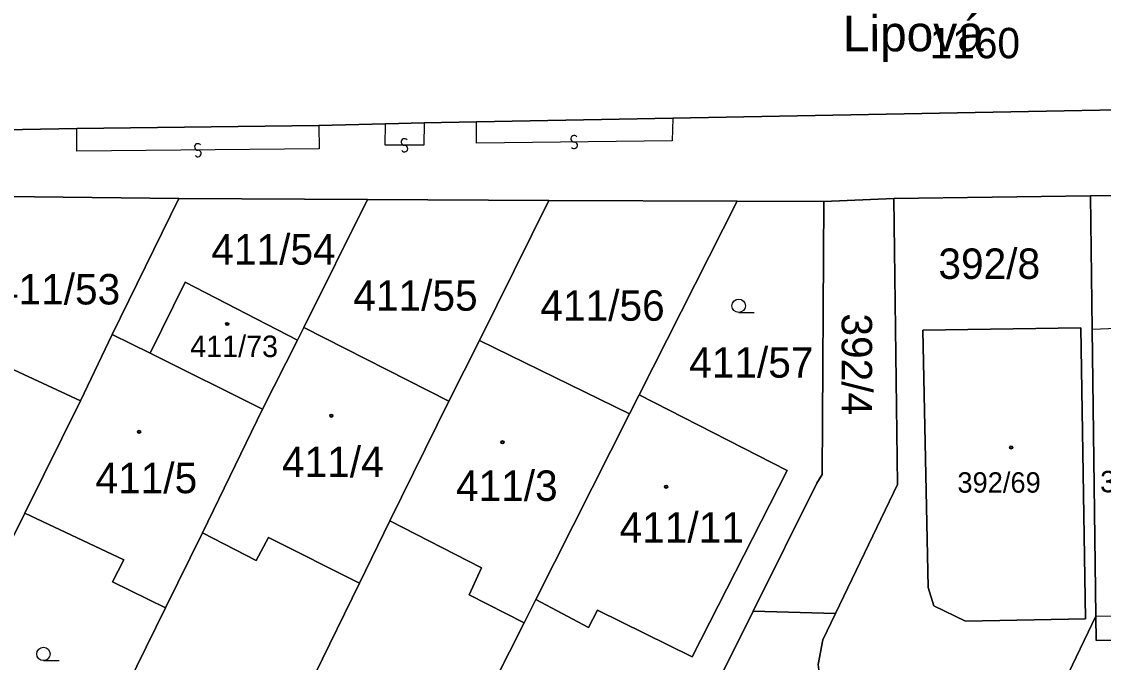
# Model space of a CAD drawing. Extents: x -600309 to -598967, y -1161267 to -1160292.
# Drawn here: x -599934.1 to -599873.6, y -1160656.9 to -1160621.1 of the extents above; entities that cross this region are included whole.
import ezdxf

# ---------------------------------------------------------------- set-up
doc = ezdxf.new("R2010")
doc.units = 0
for name, color, linetype in [('Level 1', 7, 'Continuous'), ('Level 11', 7, 'Continuous'), ('Level 13', 7, 'Continuous'), ('Level 3', 7, 'Continuous'), ('Level 4', 7, 'Continuous'), ('Level 5', 7, 'Continuous'), ('Level 60', 7, 'Continuous')]:
    doc.layers.add(name, color=color, linetype=linetype)

msp = doc.modelspace()

# ---------------------------------------------------------------- linework, layer by layer
at = {"layer": 'Level 1'}
for points in [[(-599756.08, -1160616.21), (-599758.31, -1160616.61), (-599802.91, -1160623.13), (-599821.1, -1160624.93), (-599822.46, -1160624.97), (-599824.85, -1160625.23), (-599827.9, -1160625.24), (-599856.9, -1160625.7), (-599897.68, -1160626.45)], [(-599822.46, -1160624.97), (-599824.85, -1160625.23), (-599827.9, -1160625.24), (-599856.9, -1160625.7), (-599897.68, -1160626.45), (-599908.66, -1160626.66), (-599911.59, -1160626.72), (-599913.75, -1160626.78), (-599917.47, -1160626.86), (-599931.02, -1160627.04), (-599938.13, -1160627.17), (-599938.52, -1160627.22), (-599945.69, -1160627.27), (-599947.92, -1160619.35)], [(-599897.68, -1160626.45), (-599908.66, -1160626.66)], [(-599931.02, -1160627.04), (-599938.13, -1160627.17)], [(-599931.02, -1160627.04), (-599917.47, -1160626.86)], [(-599913.75, -1160626.78), (-599917.47, -1160626.86)], [(-599913.75, -1160626.78), (-599911.59, -1160626.72)], [(-599908.66, -1160626.66), (-599911.59, -1160626.72)], [(-599935.01, -1160630.83), (-599925.3, -1160630.95)], [(-599874.33, -1160630.8), (-599885.33, -1160630.94)], [(-599868.33, -1160630.72), (-599874.33, -1160630.8)], [(-599874.33, -1160630.8), (-599874.23, -1160638.25)], [(-599925.3, -1160630.95), (-599929.03, -1160638.55)], [(-599925.3, -1160630.95), (-599914.76, -1160631)], [(-599914.76, -1160631), (-599918.31, -1160638.16)], [(-599914.76, -1160631), (-599904.62, -1160631.05)], [(-599904.62, -1160631.05), (-599908.5, -1160638.88)], [(-599904.62, -1160631.05), (-599894.08, -1160631.09)], [(-599894.08, -1160631.09), (-599899.56, -1160641.92)], [(-599894.08, -1160631.09), (-599889.23, -1160631.12)], [(-599893.19, -1160654.01), (-599889.63, -1160646.85), (-599889.34, -1160646.37), (-599889.23, -1160631.12)], [(-599885.33, -1160630.94), (-599889.23, -1160631.12)], [(-599885.33, -1160630.94), (-599885.12, -1160646.94), (-599888.59, -1160654.14)], [(-599926.91, -1160639.6), (-599924.95, -1160635.63), (-599918.67, -1160638.87)], [(-599938.77, -1160638.56), (-599930.8, -1160642.25)], [(-599930.8, -1160642.25), (-599929.03, -1160638.55)], [(-599929.03, -1160638.55), (-599926.91, -1160639.6)], [(-599918.67, -1160638.87), (-599918.31, -1160638.16)], [(-599918.31, -1160638.16), (-599910.21, -1160642.27)], [(-599883.7, -1160638.31), (-599883.4, -1160652.69), (-599883.09, -1160653.71), (-599881.31, -1160654.58), (-599874.61, -1160654.44), (-599874.86, -1160638.18), (-599883.7, -1160638.31)], [(-599874.02, -1160654.3), (-599874.23, -1160638.25)], [(-599920.62, -1160642.72), (-599918.67, -1160638.87)], [(-599910.21, -1160642.27), (-599908.5, -1160638.88)], [(-599908.5, -1160638.88), (-599900.1, -1160642.99)], [(-599926.91, -1160639.6), (-599920.62, -1160642.72)], [(-599933.92, -1160648.54), (-599930.8, -1160642.25)], [(-599913.5, -1160648.97), (-599910.21, -1160642.27)], [(-599899.56, -1160641.92), (-599891.28, -1160646.15), (-599896.6, -1160656.57), (-599901.9, -1160653.95), (-599902.4, -1160654.92), (-599905.35, -1160653.37)], [(-599900.1, -1160642.99), (-599899.56, -1160641.92)], [(-599923.99, -1160649.63), (-599920.62, -1160642.72)], [(-599900.1, -1160642.99), (-599905.35, -1160653.37)], [(-599933.92, -1160648.54), (-599935.97, -1160652.66)], [(-599926.06, -1160653.83), (-599929.01, -1160652.38), (-599928.38, -1160651.14), (-599933.92, -1160648.54)], [(-599913.5, -1160648.97), (-599915.2, -1160652.44)], [(-599906, -1160654.66), (-599909.08, -1160653.1), (-599908.38, -1160651.59), (-599913.5, -1160648.97)], [(-599923.99, -1160649.63), (-599926.06, -1160653.83)], [(-599915.2, -1160652.44), (-599920.29, -1160649.9), (-599920.98, -1160651.19), (-599923.99, -1160649.63)], [(-599922.27, -1160666.88), (-599915.2, -1160652.44)], [(-599931.96, -1160665.84), (-599926.06, -1160653.83)], [(-599905.35, -1160653.37), (-599906, -1160654.66)], [(-599897.98, -1160663.63), (-599893.19, -1160654.01)], [(-599888.59, -1160654.14), (-599893.19, -1160654.01)], [(-599888.87, -1160659.48), (-599889.38, -1160658.34), (-599889.56, -1160656.99), (-599889.3, -1160655.61), (-599888.59, -1160654.14)], [(-599874.02, -1160654.3), (-599878.84, -1160664.31)], [(-599874.02, -1160654.3), (-599874, -1160655.65), (-599868, -1160655.57)], [(-599914.18, -1160670.83), (-599906, -1160654.66)]]:
    msp.add_lwpolyline(points, dxfattribs=at)
at = {"layer": 'Level 13'}
for centre, start, end in [((-599912.689, -1160627.786), 37.15828, 269.74828), ((-599903.201, -1160627.606), 37.78615, 270.37615), ((-599903.2, -1160627.974), 218.00061, 90.09861), ((-599924.241, -1160628.066), 37.70756, 270.29756), ((-599924.24, -1160628.434), 217.92201, 90.02001), ((-599912.692, -1160628.154), 217.37273, 89.47073)]:
    msp.add_arc(centre, 0.184, start, end, dxfattribs=at)
at = {"layer": 'Level 3'}
for points in [[(-599897.68, -1160626.45), (-599897.72, -1160627.73), (-599908.67, -1160627.85), (-599908.66, -1160626.66)], [(-599917.47, -1160626.86), (-599917.46, -1160628.18), (-599931.02, -1160628.31), (-599931.02, -1160627.04)], [(-599911.59, -1160626.72), (-599911.61, -1160627.97), (-599913.76, -1160627.97), (-599913.75, -1160626.78)], [(-599874.23, -1160638.25), (-599868.24, -1160638.01)], [(-599874.02, -1160654.3), (-599868.03, -1160654.19)]]:
    msp.add_lwpolyline(points, dxfattribs=at)
at = {"layer": 'Level 5'}
for p, q in [((-599894, -1160637.32), (-599893.125, -1160637.32)), ((-599932.88, -1160656.78), (-599932.005, -1160656.78))]:
    msp.add_line(p, q, dxfattribs=at)
for centre, radius in [((-599894, -1160636.945), 0.375), ((-599922.6, -1160637.96), 0.09), ((-599922.6, -1160637.96), 0.0521), ((-599916.78, -1160643.09), 0.09), ((-599916.78, -1160643.09), 0.0521), ((-599927.53, -1160643.99), 0.09), ((-599927.53, -1160643.99), 0.0521), ((-599907.21, -1160644.57), 0.09), ((-599907.21, -1160644.57), 0.0521), ((-599878.76, -1160644.86), 0.09), ((-599878.76, -1160644.86), 0.0521), ((-599898.06, -1160647.06), 0.09), ((-599898.06, -1160647.06), 0.0521), ((-599932.88, -1160656.405), 0.375)]:
    msp.add_circle(centre, radius, dxfattribs=at)
at = {"layer": 'Level 60'}
for points in [[(-599823.51, -1160617.04), (-599822.46, -1160624.97), (-599824.85, -1160625.23), (-599827.9, -1160625.24), (-599856.9, -1160625.7), (-599897.68, -1160626.45), (-599908.66, -1160626.66), (-599911.59, -1160626.72), (-599913.75, -1160626.78), (-599917.47, -1160626.86), (-599931.02, -1160627.04), (-599938.13, -1160627.17), (-599938.52, -1160627.22), (-599945.69, -1160627.27), (-599947.92, -1160619.35)], [(-599868.33, -1160630.72), (-599874.33, -1160630.8), (-599885.33, -1160630.94), (-599889.23, -1160631.12), (-599894.08, -1160631.09), (-599904.62, -1160631.05), (-599914.76, -1160631), (-599925.3, -1160630.95), (-599935.01, -1160630.83), (-599944.67, -1160630.86), (-599945.32, -1160628.56), (-599945.69, -1160627.27), (-599938.52, -1160627.22), (-599938.13, -1160627.17), (-599931.02, -1160627.04), (-599917.47, -1160626.86), (-599913.75, -1160626.78), (-599911.59, -1160626.72), (-599908.66, -1160626.66), (-599897.68, -1160626.45), (-599856.9, -1160625.7)]]:
    msp.add_lwpolyline(points, dxfattribs=at)
for points in [[(-599929.03, -1160638.55), (-599930.8, -1160642.25), (-599938.77, -1160638.56), (-599935.01, -1160630.83), (-599925.3, -1160630.95)], [(-599885.33, -1160630.94), (-599874.33, -1160630.8), (-599874.23, -1160638.25), (-599874.02, -1160654.3), (-599878.84, -1160664.31), (-599888.87, -1160659.48), (-599889.38, -1160658.34), (-599889.56, -1160656.99), (-599889.3, -1160655.61), (-599888.59, -1160654.14), (-599885.12, -1160646.94)], [(-599874.33, -1160630.8), (-599868.33, -1160630.72), (-599868.24, -1160638.01), (-599868.03, -1160654.19), (-599868, -1160655.57), (-599874, -1160655.65), (-599874.02, -1160654.3), (-599874.23, -1160638.25)], [(-599929.03, -1160638.55), (-599925.3, -1160630.95), (-599914.76, -1160631), (-599918.31, -1160638.16), (-599918.67, -1160638.87), (-599924.95, -1160635.63), (-599926.91, -1160639.6)], [(-599908.5, -1160638.88), (-599910.21, -1160642.27), (-599918.31, -1160638.16), (-599914.76, -1160631), (-599904.62, -1160631.05)], [(-599889.63, -1160646.85), (-599893.19, -1160654.01), (-599897.98, -1160663.63), (-599899.94, -1160667.56), (-599903.81, -1160676), (-599913.11, -1160671.36), (-599914.18, -1160670.83), (-599906, -1160654.66), (-599905.35, -1160653.37), (-599902.4, -1160654.92), (-599901.9, -1160653.95), (-599896.6, -1160656.57), (-599891.28, -1160646.15), (-599899.56, -1160641.92), (-599894.08, -1160631.09), (-599889.23, -1160631.12), (-599889.34, -1160646.37)], [(-599900.1, -1160642.99), (-599908.5, -1160638.88), (-599904.62, -1160631.05), (-599894.08, -1160631.09), (-599899.56, -1160641.92)], [(-599885.33, -1160630.94), (-599885.12, -1160646.94), (-599888.59, -1160654.14), (-599893.19, -1160654.01), (-599889.63, -1160646.85), (-599889.34, -1160646.37), (-599889.23, -1160631.12)], [(-599920.62, -1160642.72), (-599926.91, -1160639.6), (-599924.95, -1160635.63), (-599918.67, -1160638.87)], [(-599930.8, -1160642.25), (-599933.92, -1160648.54), (-599935.97, -1160652.66), (-599941.32, -1160650.24), (-599941.82, -1160651.21), (-599944.35, -1160650.02), (-599940.56, -1160642.17), (-599938.77, -1160638.56)], [(-599920.62, -1160642.72), (-599923.99, -1160649.63), (-599926.06, -1160653.83), (-599929.01, -1160652.38), (-599928.38, -1160651.14), (-599933.92, -1160648.54), (-599930.8, -1160642.25), (-599929.03, -1160638.55), (-599926.91, -1160639.6)], [(-599910.21, -1160642.27), (-599913.5, -1160648.97), (-599915.2, -1160652.44), (-599920.29, -1160649.9), (-599920.98, -1160651.19), (-599923.99, -1160649.63), (-599920.62, -1160642.72), (-599918.67, -1160638.87), (-599918.31, -1160638.16)], [(-599874.86, -1160638.18), (-599883.7, -1160638.31), (-599883.4, -1160652.69), (-599883.09, -1160653.71), (-599881.31, -1160654.58), (-599874.61, -1160654.44)], [(-599883.7, -1160638.31), (-599874.86, -1160638.18), (-599874.61, -1160654.44), (-599881.31, -1160654.58), (-599883.09, -1160653.71), (-599883.4, -1160652.69)], [(-599908.5, -1160638.88), (-599900.1, -1160642.99), (-599905.35, -1160653.37), (-599906, -1160654.66), (-599909.08, -1160653.1), (-599908.38, -1160651.59), (-599913.5, -1160648.97), (-599910.21, -1160642.27)], [(-599905.35, -1160653.37), (-599900.1, -1160642.99), (-599899.56, -1160641.92), (-599891.28, -1160646.15), (-599896.6, -1160656.57), (-599901.9, -1160653.95), (-599902.4, -1160654.92)], [(-599929.01, -1160652.38), (-599926.06, -1160653.83), (-599931.96, -1160665.84), (-599940.61, -1160664.91), (-599941.07, -1160664.84), (-599941.57, -1160664.79), (-599935.97, -1160652.66), (-599933.92, -1160648.54), (-599928.38, -1160651.14)], [(-599909.08, -1160653.1), (-599906, -1160654.66), (-599914.18, -1160670.83), (-599921.42, -1160667.28), (-599922.27, -1160666.88), (-599915.2, -1160652.44), (-599913.5, -1160648.97), (-599908.38, -1160651.59)], [(-599920.29, -1160649.9), (-599915.2, -1160652.44), (-599922.27, -1160666.88), (-599931.08, -1160665.93), (-599931.96, -1160665.84), (-599926.06, -1160653.83), (-599923.99, -1160649.63), (-599920.98, -1160651.19)], [(-599893.19, -1160654.01), (-599888.59, -1160654.14), (-599889.3, -1160655.61), (-599889.56, -1160656.99), (-599889.38, -1160658.34), (-599888.87, -1160659.48), (-599888.48, -1160660.23), (-599890.81, -1160659.09), (-599891.24, -1160660.27), (-599893.86, -1160665.64), (-599897.98, -1160663.63)], [(-599878.84, -1160664.31), (-599874.02, -1160654.3), (-599874, -1160655.65), (-599868, -1160655.57), (-599868.01, -1160655.64), (-599873.51, -1160667.04)]]:
    msp.add_lwpolyline(points, close=True, dxfattribs=at)

# ---------------------------------------------------------------- texts
at = {"layer": 'Level 11'}
msp.add_text('Lipová', height=2, rotation=0.10224, dxfattribs=at).set_placement((-599888.173, -1160622.726))
at = {"layer": 'Level 4'}
for s, height, p in [('1160', 1.7, (-599883.322, -1160623.11)), ('411/54', 1.7, (-599923.49, -1160634.64)), ('392/8', 1.7, (-599882.83, -1160635.44)), ('411/53', 1.7, (-599935.54, -1160636.87)), ('411/55', 1.7, (-599915.55, -1160637.22)), ('411/56', 1.7, (-599905.09, -1160637.78)), ('411/73', 1.2, (-599924.67, -1160639.81)), ('411/57', 1.7, (-599896.77, -1160640.96)), ('411/4', 1.7, (-599919.54, -1160646.52)), ('411/5', 1.7, (-599929.97, -1160647.42)), ('411/3', 1.7, (-599909.81, -1160647.85)), ('392/69', 1.14, (-599881.769, -1160647.39)), ('392/36', 1.2, (-599873.79, -1160647.37)), ('411/11', 1.7, (-599900.66, -1160650.18))]:
    msp.add_text(s, height=height, dxfattribs=at).set_placement(p)
msp.add_text('392/4', height=1.7, rotation=270, dxfattribs=at).set_placement((-599888.24, -1160637.37))

doc.saveas('drawing.dxf')
